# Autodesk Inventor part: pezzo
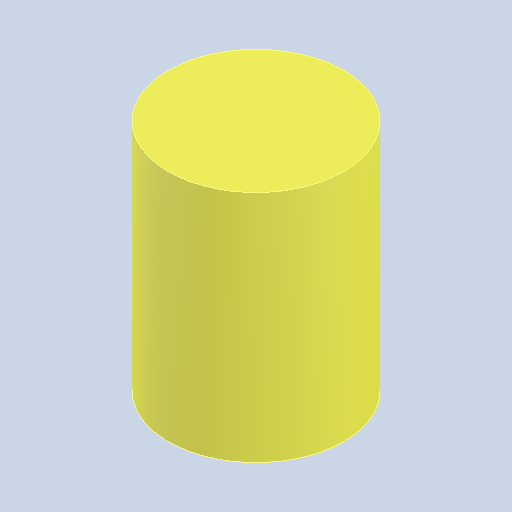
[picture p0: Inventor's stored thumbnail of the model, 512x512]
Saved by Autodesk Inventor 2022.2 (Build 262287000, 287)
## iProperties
Created: 2024-10
Part Number: pezzo
Material: Alluminio 6061
Document SubType Name: Modeling
Designer: 18907419
Density: 2.7 g/cm^3
Appearance: Default
Author: 18907419
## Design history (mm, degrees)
feature "Solido1"
node "Solido2"
